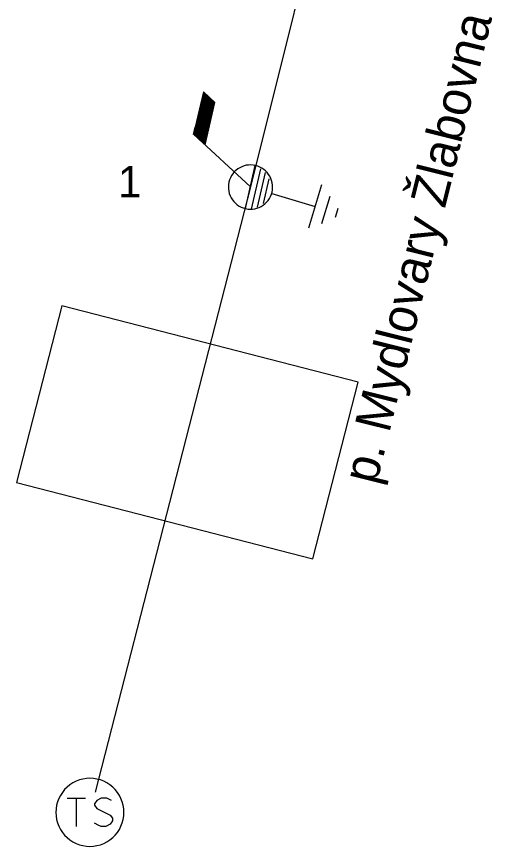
# Model space of a CAD drawing. Extents: x -763667 to -762498, y -1153000 to -1152000.
# Drawn here: x -762639.64 to -762612.32, y -1152849.86 to -1152803.8 of the extents above; entities that cross this region are included whole.
import ezdxf

# ---------------------------------------------------------------- set-up
doc = ezdxf.new("R2010")
doc.units = 0
for name, color, linetype in [('Vrstva 11', 7, 'Continuous'), ('Vrstva 13', 7, 'Continuous'), ('Vrstva 14', 7, 'Continuous'), ('Vrstva 15', 7, 'Continuous'), ('Vrstva 25', 7, 'Continuous'), ('Vrstva 35', 7, 'Continuous'), ('Vrstva 4', 7, 'Continuous'), ('Vrstva 59', 7, 'Continuous')]:
    doc.layers.add(name, color=color, linetype=linetype)

msp = doc.modelspace()

# ---------------------------------------------------------------- linework, layer by layer
at = {"layer": 'Vrstva 11'}
for p, q in [((-762629.764, -1152810.373), (-762629.221, -1152808.019)), ((-762629.722, -1152810.412), (-762629.179, -1152808.058)), ((-762629.68, -1152810.451), (-762629.136, -1152808.098)), ((-762629.637, -1152810.49), (-762629.094, -1152808.137)), ((-762629.595, -1152810.529), (-762629.052, -1152808.177)), ((-762629.553, -1152810.568), (-762629.01, -1152808.216)), ((-762629.51, -1152810.608), (-762628.967, -1152808.255)), ((-762629.468, -1152810.647), (-762628.925, -1152808.295)), ((-762629.426, -1152810.686), (-762628.883, -1152808.334)), ((-762629.384, -1152810.725), (-762628.841, -1152808.373)), ((-762629.341, -1152810.764), (-762628.798, -1152808.413)), ((-762629.299, -1152810.803), (-762628.756, -1152808.452)), ((-762629.257, -1152810.842), (-762628.714, -1152808.492)), ((-762629.214, -1152810.881), (-762628.672, -1152808.531)), ((-762629.806, -1152810.334), (-762629.714, -1152809.933))]:
    msp.add_line(p, q, dxfattribs=at)
msp.add_lwpolyline([(-762629.26, -1152807.983), (-762629.807, -1152810.333), (-762629.175, -1152810.918), (-762628.633, -1152808.567)], close=True, dxfattribs=at)
msp.add_lwpolyline([(-762629.807, -1152810.333), (-762626.65, -1152813.25)], dxfattribs=at)
at = {"layer": 'Vrstva 13'}
for points in [[(-762626.373, -1152812.063), (-762626.5, -1152812.041), (-762626.628, -1152812.032), (-762626.756, -1152812.036), (-762626.884, -1152812.054), (-762627.008, -1152812.085), (-762627.129, -1152812.129), (-762627.245, -1152812.185), (-762627.354, -1152812.253), (-762627.455, -1152812.332), (-762627.548, -1152812.422), (-762627.63, -1152812.52), (-762627.702, -1152812.627), (-762627.763, -1152812.741), (-762627.811, -1152812.86), (-762627.846, -1152812.984), (-762627.868, -1152813.11), (-762627.877, -1152813.238), (-762627.873, -1152813.367), (-762627.855, -1152813.494), (-762627.824, -1152813.619), (-762627.78, -1152813.74), (-762627.724, -1152813.855), (-762627.655, -1152813.964), (-762627.576, -1152814.066), (-762627.487, -1152814.158), (-762627.389, -1152814.24), (-762627.282, -1152814.313), (-762627.168, -1152814.373), (-762627.049, -1152814.421), (-762626.926, -1152814.457), (-762626.799, -1152814.479), (-762626.671, -1152814.488), (-762626.542, -1152814.483), (-762626.415, -1152814.465), (-762626.29, -1152814.434), (-762626.17, -1152814.391), (-762626.054, -1152814.334), (-762625.945, -1152814.266), (-762625.843, -1152814.187), (-762625.751, -1152814.098), (-762625.668, -1152813.999), (-762625.596, -1152813.893), (-762625.536, -1152813.779), (-762625.488, -1152813.659), (-762625.453, -1152813.536), (-762625.43, -1152813.409), (-762625.421, -1152813.281), (-762625.426, -1152813.153), (-762625.443, -1152813.025), (-762625.474, -1152812.901), (-762625.518, -1152812.779), (-762625.575, -1152812.664), (-762625.643, -1152812.555), (-762625.722, -1152812.454), (-762625.812, -1152812.361), (-762625.91, -1152812.279), (-762626.017, -1152812.207), (-762626.13, -1152812.147), (-762626.249, -1152812.098), (-762626.373, -1152812.063)], [(-762626.934, -1152814.458), (-762626.381, -1152812.065)], [(-762626.585, -1152814.48), (-762626.071, -1152812.254)], [(-762626.265, -1152814.376), (-762625.82, -1152812.45)], [(-762625.924, -1152814.179), (-762625.605, -1152812.796)]]:
    msp.add_lwpolyline(points, dxfattribs=at)
at = {"layer": 'Vrstva 15'}
for points in [[(-762622.7, -1152813.146), (-762623.431, -1152815.537)], [(-762625.456, -1152813.611), (-762623.065, -1152814.342)], [(-762622.248, -1152813.789), (-762622.708, -1152815.295)], [(-762621.792, -1152814.453), (-762621.87, -1152814.707)], [(-762621.87, -1152814.707), (-762621.945, -1152814.952)]]:
    msp.add_lwpolyline(points, dxfattribs=at)
at = {"layer": 'Vrstva 25'}
for points in [[(-762633.677, -1152847.971), (-762633.688, -1152847.774), (-762633.719, -1152847.578), (-762633.77, -1152847.387), (-762633.842, -1152847.202), (-762633.931, -1152847.027), (-762634.039, -1152846.861), (-762634.163, -1152846.707), (-762634.303, -1152846.567), (-762634.457, -1152846.443), (-762634.623, -1152846.335), (-762634.799, -1152846.245), (-762634.983, -1152846.174), (-762635.175, -1152846.123), (-762635.37, -1152846.092), (-762635.567, -1152846.081), (-762635.765, -1152846.092), (-762635.961, -1152846.123), (-762636.151, -1152846.174), (-762636.337, -1152846.245), (-762636.512, -1152846.335), (-762636.678, -1152846.443), (-762636.832, -1152846.567), (-762636.972, -1152846.707), (-762637.096, -1152846.861), (-762637.204, -1152847.027), (-762637.294, -1152847.202), (-762637.365, -1152847.387), (-762637.416, -1152847.578), (-762637.447, -1152847.774), (-762637.458, -1152847.971), (-762637.447, -1152848.169), (-762637.416, -1152848.365), (-762637.365, -1152848.555), (-762637.294, -1152848.74), (-762637.204, -1152848.916), (-762637.096, -1152849.082), (-762636.971, -1152849.236), (-762636.832, -1152849.375), (-762636.678, -1152849.5), (-762636.512, -1152849.608), (-762636.336, -1152849.698), (-762636.151, -1152849.769), (-762635.961, -1152849.82), (-762635.765, -1152849.851), (-762635.567, -1152849.862), (-762635.37, -1152849.851), (-762635.175, -1152849.82), (-762634.983, -1152849.769), (-762634.799, -1152849.698), (-762634.623, -1152849.608), (-762634.457, -1152849.5), (-762634.303, -1152849.375), (-762634.163, -1152849.236), (-762634.039, -1152849.082), (-762633.931, -1152848.916), (-762633.842, -1152848.74), (-762633.77, -1152848.555), (-762633.719, -1152848.365), (-762633.688, -1152848.169), (-762633.677, -1152847.971)], [(-762636.829, -1152847.188), (-762635.821, -1152847.188)], [(-762636.325, -1152847.188), (-762636.325, -1152848.762)], [(-762634.372, -1152847.314), (-762634.624, -1152847.188), (-762634.939, -1152847.188), (-762635.191, -1152847.314), (-762635.317, -1152847.502), (-762635.317, -1152847.566), (-762635.191, -1152847.754), (-762634.435, -1152848.132), (-762634.309, -1152848.29), (-762634.309, -1152848.448), (-762634.435, -1152848.636), (-762634.687, -1152848.762), (-762634.939, -1152848.762), (-762635.065, -1152848.7), (-762635.317, -1152848.574)]]:
    msp.add_lwpolyline(points, dxfattribs=at)
at = {"layer": 'Vrstva 35'}
msp.add_lwpolyline([(-762639.64, -1152829.66), (-762623.18, -1152833.89), (-762620.66, -1152824.09), (-762637.12, -1152819.86)], close=True, dxfattribs=at)
at = {"layer": 'Vrstva 4'}
for points in [[(-762616.99, -1152774.51), (-762626.65, -1152813.25)], [(-762626.65, -1152813.25), (-762635.28, -1152846.86)]]:
    msp.add_lwpolyline(points, dxfattribs=at)

# ---------------------------------------------------------------- texts
at = {"layer": 'Vrstva 14'}
msp.add_text('1', height=1.74, dxfattribs=at).set_placement((-762634, -1152813.83))
at = {"layer": 'Vrstva 59'}
msp.add_text('p. Mydlovary Žlabovna TS', height=1.98857, rotation=76.0742, dxfattribs=at).set_placement((-762619.66, -1152829.83))

doc.saveas('drawing.dxf')
